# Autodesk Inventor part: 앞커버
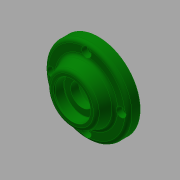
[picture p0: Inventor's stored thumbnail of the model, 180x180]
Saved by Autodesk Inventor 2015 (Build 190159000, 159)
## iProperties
Created: 2017-08
Part Number: 앞커버
Material: 알루미늄 6061
Document SubType Name: Modeling
Designer: mduedu
Density: 1 g/cm^3
Appearance: 진녹색
Author: mduedu
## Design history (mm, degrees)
sketch "스케치1"
  geometry: C1 r 35 at (0, 0); 1 further point
  constraints: 1 centre point, 1 coincident
  dimensions: "d0" = 70 diameter of C1
extrude "돌출1" new body sketch "스케치1" distance "d1" = 10; taper "d2" = 0 deg
sketch "스케치2"
  geometry: C1 r 24 at (0, 0); 1 further point
  constraints: 1 centre point, 1 coincident
  dimensions: "d3" = 48 diameter of C1
node "작업 평면1"
sketch "스케치3"
  geometry: C1 r 20 at (0, 0); 1 further point
  constraints: 1 centre point, 1 coincident
  dimensions: "d5" = 40 diameter of C1
feature "로프트1" sketch "스케치3" dims "d6" = 0, "d7" = 90 deg, "d8" = 0, "d9" = 90 deg
sketch "스케치4"
  geometry: C1 r 24 at (0, 0) reference; 1 further point
extrude "돌출2" join sketch "스케치4" distance "d10" = 8; taper "d11" = 0 deg
hole "구멍1" diameter "d14" = 40; stored, may be unused: countersink angle "d18" = 90 deg, drill point angle "d20" = 0 deg; dims "d12" = 10, "d13" = 10, "d15" = 6, "d16" = 4, "d17" = 2, "d19" = 12
hole "구멍2" diameter "d23" = 34; stored, may be unused: countersink angle "d27" = 90 deg, drill point angle "d29" = 0 deg; dims "d21" = 10, "d22" = 10, "d24" = 6, "d25" = 4, "d26" = 2, "d28" = 3
hole "구멍3" diameter "d32" = 19; stored, may be unused: countersink angle "d36" = 90 deg, drill point angle "d38" = 0 deg; dims "d30" = 10, "d31" = 10, "d33" = 6, "d34" = 4, "d35" = 2, "d37" = 3
chamfer "모따기1" distance "d39" = 1; stored, may be unused: second distance "d40" = 2, angle "d41" = 45 deg
sketch "스케치5"
  geometry: C1 r 15 at (0, 0); 1 further point
  constraints: 1 centre point, 1 coincident
  dimensions: "d42" = 30 diameter of C1
extrude "돌출3" cut sketch "스케치5" distance "d43" = 8.3; taper "d44" = 0 deg
chamfer "모따기2" distance "d47" = 0.8; stored, may be unused: second distance "d48" = 2, angle "d49" = 30 deg
fillet "모깎기1" dims "d50" = 0.3
fillet "모깎기2" dims "d51" = 0.3
fillet "모깎기3" dims "d52" = 3
sketch "스케치6" dims "d53" = 58
  geometry: 6 further points
  constraints: 2 vertical alignment, 1 coincident, 7 other
  dimensions: "d56" = 360 deg dimension on point (0, 0) point (0, 29) (derived)
sketch "스케치9" dims "d85" = 58 (derived)
  geometry: 6 further points
  constraints: 1 coincident, 1 vertical alignment, 6 other
hole "구멍6" sketch "스케치9" at (-29, 0), (0, -29), (29, 0), (0, 29) diameter "d72" = 4.5; stored, may be unused: countersink angle "d76" = 90 deg, drill point angle "d78" = 0 deg; dims "d73" = 6, "d74" = 8, "d75" = 4.6, "d77" = 8
fillet "모깎기4" dims "d79" = 3
fillet "모깎기5" dims "d80" = 3
fillet "모깎기6" dims "d81" = 3
node "솔리드1"
other parameters: "d4" = 12
